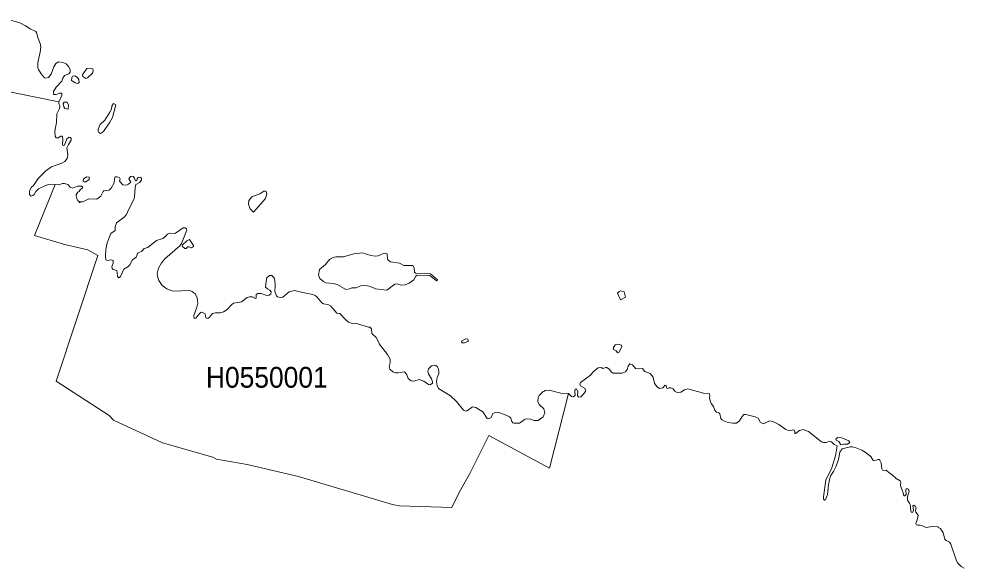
# Model space of a CAD drawing. Extents: x 369010 to 739155, y 6377141 to 6616555.
# Drawn here: x 445236 to 449782, y 6490349 to 6492992 of the extents above; entities that cross this region are included whole.
import ezdxf
from ezdxf.enums import TextEntityAlignment as Align

# ---------------------------------------------------------------- set-up
doc = ezdxf.new("R2010")
doc.units = 0
doc.header["$LTSCALE"] = 40
doc.layers.add('1', color=7, linetype='Continuous', lineweight=13)
doc.layers.add('2', color=7, linetype='Continuous')

msp = doc.modelspace()

# ---------------------------------------------------------------- linework, layer by layer
at = {"layer": '1'}
for points in [[(445001.04, 6492679.83), (445428.7, 6492593.93), (445443.43, 6492623.72), (445443.43, 6492631), (445440.12, 6492634.81), (445431.18, 6492635.14), (445415.13, 6492629.18), (445406.19, 6492628.19), (445403.38, 6492631), (445402.38, 6492642.59), (445416.12, 6492664.27), (445443.76, 6492693.4), (445447.57, 6492707.13), (445456.17, 6492719.38), (445477.19, 6492727.32), (445483.65, 6492735.27), (445483.65, 6492748.18), (445474.71, 6492763.24), (445464.45, 6492775.32), (445448.56, 6492782.93), (445427.71, 6492785.91), (445413.64, 6492778.13), (445405.03, 6492762.25), (445391.13, 6492725.67), (445379.05, 6492709.78), (445365.31, 6492706.8), (445359.85, 6492709.45), (445342.97, 6492728.32), (445330.39, 6492748.84), (445327.91, 6492757.12), (445327.91, 6492782.11), (445339, 6492831.92), (445341.64, 6492856.91), (445338.66, 6492873.46), (445328.9, 6492898.46), (445321.45, 6492927.58), (445317.31, 6492932.05), (445290.17, 6492944.96), (445268.66, 6492959.69), (445241.18, 6492973.93), (445174.65, 6492992.3)], [(447914.57, 6491182.34), (447906.29, 6491174.07), (447896.03, 6491174.73), (447882.29, 6491190.29), (447881.96, 6491190.29), (447791.43, 6490829.82), (447498.66, 6490987.88), (447407.63, 6490804.33), (447355.5, 6490713.64), (447321.07, 6490640.65), (447068.68, 6490648.76), (447034.75, 6490655.71), (446916.74, 6490690.96), (446582.59, 6490790.6), (446335.49, 6490848.19), (446188.36, 6490873.85), (446170.32, 6490882.45), (445928.02, 6490951.47), (445691.52, 6491062.02), (445671, 6491084.37), (445416.12, 6491248.55), (445616.05, 6491854.46), (445567.72, 6491880.77), (445449.22, 6491907.75), (445451.87, 6491907.75), (445311.19, 6491949.62), (445410.82, 6492195.39), (445399.9, 6492196.88), (445378.72, 6492195.23), (445364.65, 6492191.09), (445330.39, 6492173.88), (445317.98, 6492160.97), (445310.53, 6492147.9), (445304.24, 6492141.77), (445294.81, 6492138.63), (445287.19, 6492146.74), (445287.19, 6492165.27), (445296.46, 6492182.49), (445306.06, 6492189.77), (445329.4, 6492224.03), (445365.64, 6492261.76), (445393.45, 6492279.97), (445442.77, 6492297.35), (445458.32, 6492305.95), (445469.25, 6492320.68), (445471.56, 6492338.56), (445467.92, 6492371.82), (445474.71, 6492388.54), (445488.11, 6492409.06), (445488.45, 6492416.67), (445484.31, 6492421.8), (445479.18, 6492422.8), (445467.59, 6492414.69), (445455.51, 6492384.4), (445450.71, 6492382.75), (445447.57, 6492384.73), (445446.24, 6492390.03), (445447.9, 6492410.88), (445446.57, 6492423.96), (445443.43, 6492427.27), (445437.97, 6492427.27), (445425.39, 6492419.82), (445416.12, 6492420.15), (445411.32, 6492427.27), (445409.17, 6492452.42), (445417.44, 6492494.13), (445419.76, 6492535.67), (445431.84, 6492560.66), (445433.17, 6492571.92), (445429.03, 6492585.65), (445428.7, 6492593.93), (445001.04, 6492679.83)], [(445806.54, 6491860.91), (445802.08, 6491847.17), (445783.7, 6491832.78), (445770.96, 6491808.12), (445760.7, 6491799.18), (445741.17, 6491788.25), (445725.28, 6491751.84), (445720.48, 6491747.04), (445717.5, 6491746.71), (445711.54, 6491752.51), (445710.22, 6491772.37), (445707.24, 6491780.97), (445690.03, 6491786.1), (445686.22, 6491790.9), (445683.91, 6491800.83), (445690.36, 6491817.05), (445689.7, 6491828.97), (445681.42, 6491832.11), (445661.56, 6491830.13), (445655.77, 6491833.44), (445652.96, 6491850.98), (445655.77, 6491882.92), (445661.56, 6491915.03), (445678.44, 6491959.22), (445699.96, 6491974.45), (445699.96, 6491992.49), (445706.74, 6492010.36), (445742.82, 6492038.17), (445754.08, 6492050.25), (445763.68, 6492073.09), (445789.83, 6492123.9), (445793.3, 6492136.64), (445795.62, 6492179.84), (445800.09, 6492194.57), (445816.47, 6492204.83), (445826.57, 6492216.08), (445826.57, 6492224.69), (445821.27, 6492231.14), (445811.34, 6492229.82), (445806.21, 6492223.03), (445804.23, 6492215.09), (445800.42, 6492213.43), (445795.95, 6492216.08), (445792.48, 6492225.35), (445786.35, 6492233.63), (445782.55, 6492235.28), (445774.11, 6492233.63), (445765.83, 6492222.54), (445775.43, 6492206.15), (445764.84, 6492196.55), (445754.41, 6492191.42), (445737.03, 6492193.74), (445721.14, 6492210.62), (445723.3, 6492222.7), (445720.48, 6492229.49), (445709.56, 6492232.96), (445700.62, 6492232.14), (445696.15, 6492222.21), (445694.5, 6492203.01), (445680.76, 6492177.35), (445671.82, 6492168.75), (445646.17, 6492164.61), (445642.36, 6492161.63), (445631.44, 6492138.63), (445611.25, 6492125.22), (445573.85, 6492125.88), (445566.56, 6492123.9), (445543.89, 6492111.15), (445531.64, 6492111.15), (445529.16, 6492107.35), (445526.18, 6492111.82), (445528.17, 6492112.48), (445520.39, 6492116.28), (445514.76, 6492127.37), (445511.45, 6492140.28), (445512.11, 6492146.57), (445519.89, 6492157.83), (445527.17, 6492161.63), (445531.97, 6492169.91), (445542.9, 6492178.68), (445543.89, 6492182.15), (445537.43, 6492186.95), (445518.24, 6492186.95), (445494.24, 6492178.35), (445483.65, 6492183.15), (445471.56, 6492195.56), (445456.17, 6492200.69), (445446.24, 6492200.36), (445428.04, 6492193.08), (445410.82, 6492195.39)], [(445410.82, 6492195.39), (445311.19, 6491949.62), (445451.87, 6491907.75), (445449.22, 6491907.75), (445567.72, 6491880.77), (445616.05, 6491854.46), (445416.12, 6491248.55), (445671, 6491084.37), (445691.52, 6491062.02), (445928.02, 6490951.47), (446170.32, 6490882.45), (446188.36, 6490873.85), (446335.49, 6490848.19), (446582.59, 6490790.6), (446916.74, 6490690.96), (447034.75, 6490655.71), (447068.68, 6490648.76), (447321.07, 6490640.65), (447355.5, 6490713.64), (447407.63, 6490804.33), (447498.66, 6490987.88), (447791.43, 6490829.82), (447881.96, 6491190.29), (447846.05, 6491190.62), (447788.62, 6491205.68), (447769.42, 6491203.69), (447766.77, 6491200.88), (447759.99, 6491199.23), (447741.78, 6491180.69), (447735.49, 6491169.6), (447733.84, 6491150.9), (447740.79, 6491136.17), (447763.3, 6491116.47), (447768.1, 6491096.94), (447759.49, 6491078.08), (447735.99, 6491060.37), (447729.7, 6491058.88), (447716.79, 6491060.04), (447699.91, 6491066.16), (447677.9, 6491067.82), (447671.11, 6491065.17), (447651.25, 6491049.28), (447645.79, 6491046.96), (447620.3, 6491046.3), (447614.84, 6491048.95), (447608.72, 6491055.57), (447604.25, 6491070.3), (447598.79, 6491077.08), (447573.8, 6491088.5), (447547.31, 6491097.61), (447533.25, 6491099.76), (447518.19, 6491093.3), (447509.91, 6491074.11), (447497.33, 6491068.48), (447490.71, 6491069.47), (447469.86, 6491102.08), (447435.6, 6491122.76), (447419.38, 6491125.08), (447394.39, 6491106.21), (447387.93, 6491105.22), (447376.18, 6491109.36), (447342.92, 6491150.57), (447313.79, 6491178.87), (447256.19, 6491214.29), (447250.07, 6491228.35), (447247.26, 6491247.55), (447250.07, 6491266.75), (447257.35, 6491285.95), (447258.34, 6491298.86), (447255.53, 6491311.6), (447252.06, 6491318.06), (447243.28, 6491324.02), (447235.67, 6491325.67), (447222.26, 6491322.86), (447208.86, 6491308.96), (447205.55, 6491296.21), (447208.2, 6491283.47), (447222.26, 6491259.8), (447227.73, 6491246.39), (447227.73, 6491238.62), (447216.8, 6491232), (447207.54, 6491232.82), (447185.69, 6491249.21), (447162.68, 6491257.15), (447137.2, 6491248.55), (447125.28, 6491249.87), (447111.21, 6491261.29), (447104.26, 6491279.66), (447095.82, 6491291.41), (447090.36, 6491293.73), (447062.22, 6491288.27), (447049.48, 6491289.59), (447037.07, 6491294.06), (447022.83, 6491306.14), (447018.36, 6491319.22), (447024.49, 6491338.42), (447023.83, 6491355.13), (447010.42, 6491376.81), (446970.7, 6491428.12), (446970.7, 6491431.92)], [(446970.7, 6491431.92), (446956.96, 6491459.4), (446935.28, 6491478.27), (446934.29, 6491500.28), (446925.35, 6491508.39), (446918.9, 6491508.39), (446861.3, 6491526.26), (446835.81, 6491528.74), (446823.57, 6491533.54), (446810.49, 6491543.47), (446781.2, 6491574.26), (446766.96, 6491576.91), (446737.83, 6491609.18), (446724.1, 6491618.12), (446703.24, 6491620.93), (446695.3, 6491625.4), (446670.97, 6491654.86), (446662.7, 6491661.64), (446651.77, 6491666.44), (446602.78, 6491675.38), (446562.57, 6491685.31), (446537.57, 6491679.19), (446506.79, 6491653.04), (446495.37, 6491651.71), (446481.97, 6491655.52), (446476.83, 6491660.32), (446468.73, 6491680.51), (446470.38, 6491709.64), (446469.06, 6491735.13), (446464.59, 6491745.72), (446453.66, 6491756.97), (446443.57, 6491757.31), (446430.66, 6491746.05), (446428.18, 6491741.25), (446424.37, 6491700.87), (446433.31, 6491692.59), (446444.73, 6491687.13), (446450.85, 6491679.19), (446448.86, 6491668.6), (446440.59, 6491662.31), (446430, 6491660.98), (446403.19, 6491671.57), (446385.97, 6491671.24), (446379.19, 6491666.78), (446379.19, 6491647.91), (446376.04, 6491646.91), (446360.32, 6491654.2), (446346.25, 6491655.52), (446334.67, 6491651.38), (446308.19, 6491631.52), (446270.12, 6491623.58), (446259.53, 6491616.46), (446239.34, 6491594.45), (446221.46, 6491583.2), (446205.74, 6491577.07), (446183.07, 6491578.06), (446168, 6491574.26), (446152.61, 6491555.39), (446145.99, 6491550.26), (446136.72, 6491554.4), (446132.59, 6491573.27), (446115.21, 6491581.04), (446106.93, 6491575.91), (446088.4, 6491552.58), (446080.62, 6491551.25), (446078.14, 6491564.33), (446093.53, 6491604.71), (446097.33, 6491623.91), (446095.35, 6491649.4), (446086.74, 6491668.26), (446070.52, 6491681.17), (446057.61, 6491685.64), (445980.82, 6491682), (445968.08, 6491684.98), (445948.88, 6491692.92), (445926.87, 6491709.64), (445910.48, 6491732.65), (445904.69, 6491748.04), (445902.54, 6491767.24), (445908.16, 6491792.72), (445922.89, 6491818.05), (445939.28, 6491837.24), (446011.6, 6491900.63), (446019.88, 6491912.05), (446045.2, 6491975.11), (446043.21, 6491981.89), (446037.09, 6491986.36), (446027.49, 6491986.36), (445991.08, 6491961.04), (445984.63, 6491958.89), (445962.95, 6491961.37), (445951.69, 6491955.91), (445944.41, 6491947.3), (445929.35, 6491936.05), (445898.56, 6491926.45), (445857.35, 6491892.85), (445838.82, 6491887.56), (445827.23, 6491872.5), (445810.68, 6491866.7), (445806.54, 6491860.91)], [(449150.06, 6490831.48), (449168.1, 6490889.24), (449175.38, 6490937.4), (449161.64, 6490944.35), (449149.06, 6490956.93), (449138.8, 6490959.58), (449122.09, 6490953.12), (449109.34, 6490954.11), (449100.07, 6490956.93), (449036.85, 6491006.91), (449011.86, 6491016.68), (448993.82, 6491010.88), (448975.78, 6490997.31), (448971.97, 6490997.64), (448971.31, 6491004.76), (448967.84, 6491013.03), (448965.02, 6491014.36), (448944.67, 6491010.22), (448928.78, 6491017.17), (448894.52, 6491041.17), (448866.05, 6491055.57), (448849.5, 6491057.55), (448821.03, 6491043.49), (448806.63, 6491050.77), (448795.71, 6491070.96), (448780.32, 6491077.75), (448735.63, 6491088.84), (448726.53, 6491088.34), (448717.92, 6491078.9), (448704.85, 6491057.89), (448690.78, 6491047.62), (448673.57, 6491046.96), (448650.4, 6491050.44), (448633.19, 6491055.9), (448622.26, 6491062.69), (448615.97, 6491069.97), (448610.84, 6491091.81), (448606.71, 6491096.61), (448594.79, 6491100.42), (448586.51, 6491109.69), (448580.72, 6491127.23), (448569.14, 6491141.3), (448563.51, 6491154.21), (448560.2, 6491169.93), (448562.85, 6491179.7), (448561.52, 6491186.81), (448559.04, 6491189.63), (448532.06, 6491190.62), (448457.26, 6491212.47), (448439.88, 6491207), (448422.67, 6491196.74), (448405.45, 6491194.1), (448393.87, 6491200.88), (448386.25, 6491212.14), (448375.5, 6491217.6), (448366.39, 6491216.94), (448360.44, 6491213.79), (448356.13, 6491214.78), (448352, 6491227.2), (448346.86, 6491229.35), (448336.27, 6491216.94), (448320.55, 6491213.29), (448308.47, 6491221.4), (448296.22, 6491237.95), (448290.59, 6491268.41), (448275.2, 6491285.95), (448249.22, 6491295.22), (448238.46, 6491309.29), (448214.13, 6491308.46), (448205.03, 6491310.28), (448190.63, 6491327.82), (448177.22, 6491331.79), (448169.28, 6491320.87), (448164.48, 6491305.81), (448156.2, 6491293.73), (448139.82, 6491287.94), (448097.62, 6491287.61), (448089.67, 6491292.41), (448078.09, 6491306.14), (448066.5, 6491315.08), (448061.37, 6491315.08), (448046.97, 6491309.29), (448039.03, 6491314.75), (448025.29, 6491312.6), (448002.29, 6491295.22), (447987.56, 6491278.34), (447939.56, 6491242.75), (447937.24, 6491234.15), (447939.56, 6491226.2), (447961.9, 6491212.96), (447963.89, 6491199.56), (447951.14, 6491183.01), (447940.88, 6491174.07), (447930.29, 6491172.08), (447926.15, 6491179.2), (447926.48, 6491198.4), (447920.36, 6491212.47), (447913.58, 6491211.14), (447912.75, 6491199.56), (447914.57, 6491182.34)], [(449786.91, 6490349.36), (449771.85, 6490356.65), (449756.79, 6490372.37), (449750.67, 6490384.28), (449723.36, 6490463.89), (449716.24, 6490474.48), (449700.36, 6490482.43), (449694.56, 6490487.89), (449685.13, 6490519.34), (449673.38, 6490539.2), (449662.46, 6490545.32), (449661.79, 6490547.31), (449632.83, 6490548.8), (449604.03, 6490544.66), (449592.45, 6490550.12), (449584.5, 6490552.11), (449580.86, 6490554.92), (449575.24, 6490556.24), (449564.64, 6490555.58), (449558.19, 6490557.9), (449554.55, 6490563.36), (449555.21, 6490569.15), (449562.33, 6490586.36), (449565.14, 6490604.07), (449554.38, 6490618.8), (449553.39, 6490628.07), (449555.54, 6490639.66), (449552.4, 6490646.11), (449544.12, 6490652.24), (449539.49, 6490649.92), (449542.47, 6490628.07), (449539.16, 6490617.81), (449536.67, 6490616.16), (449531.54, 6490618.8), (449528.56, 6490635.85), (449529.23, 6490648.59), (449523.76, 6490662.5), (449514.5, 6490675.9), (449513.5, 6490680.7), (449514.83, 6490692.29), (449522.61, 6490718.93), (449519.29, 6490728.53), (449516.48, 6490731.02), (449507.71, 6490730.52), (449506.22, 6490727.54), (449507.38, 6490703.54), (449501.09, 6490696.43), (449498.11, 6490697.75), (449495.63, 6490702.22), (449493.64, 6490713.14), (449489.84, 6490719.26), (449480.24, 6490746.74), (449481.73, 6490762.79), (449478.58, 6490768.58), (449460.38, 6490780.17), (449438.2, 6490799.04), (449425.29, 6490807.48), (449412.21, 6490819.89), (449404.44, 6490818.4), (449394.5, 6490819.89), (449390.04, 6490827.67), (449386.89, 6490856.47), (449380.77, 6490869.38), (449377.46, 6490871.86), (449371.17, 6490872.19), (449355.45, 6490865.9), (449348.99, 6490867.06), (449338.07, 6490886.09), (449310.76, 6490906.62), (449293.55, 6490917.21), (449261.44, 6490930.28), (449249.19, 6490933.59), (449237.61, 6490933.59), (449199.54, 6490922.67), (449188.62, 6490906.62), (449182.16, 6490871.86), (449169.25, 6490837.27), (449157.17, 6490813.6), (449144.92, 6490794.24), (449140.13, 6490781.49), (449133.67, 6490749.39), (449128.54, 6490704.37), (449118.61, 6490677.23), (449115.13, 6490675.9), (449112.49, 6490677.56), (449110.33, 6490683.35), (449110, 6490691.63), (449120.93, 6490772.39), (449150.06, 6490831.48)]]:
    msp.add_lwpolyline(points, dxfattribs=at)
for points in [[(445578.98, 6492755.13), (445562.76, 6492754.14), (445543.23, 6492722.86), (445544.72, 6492715.74), (445558.78, 6492706.14), (445566.23, 6492709.12), (445590.89, 6492731.79), (445594.7, 6492741.72), (445592.38, 6492751.65)], [(445505.49, 6492718.06), (445494.9, 6492716.07), (445490.76, 6492710.94), (445489.77, 6492696.54), (445507.97, 6492684.13), (445517.9, 6492681.31), (445527.17, 6492685.45), (445524.36, 6492700.51), (445517.9, 6492710.94)], [(445470.9, 6492587.8), (445466.43, 6492591.94), (445454.85, 6492591.94), (445449.06, 6492584.33), (445452.37, 6492568.94), (445458.32, 6492560.99), (445473.05, 6492558.01), (445476.03, 6492577.87)], [(445643.69, 6492450.6), (445674.64, 6492494.79), (445687.22, 6492518.46), (445702.44, 6492578.87), (445692.51, 6492584.66), (445684.24, 6492573.07), (445682.75, 6492558.01), (445674.97, 6492542.79), (445650.64, 6492504.39), (445628.3, 6492484.53), (445618.37, 6492461.53), (445618.03, 6492452.26), (445621.51, 6492445.14), (445629.62, 6492441.33)], [(445564.25, 6492232.63), (445547.36, 6492223.36), (445545.71, 6492210.95), (445550.18, 6492207.48), (445559.12, 6492207.48), (445574.18, 6492219.56), (445574.84, 6492230.15)], [(446423.38, 6492163.29), (446415.27, 6492162.63), (446397.06, 6492150.21), (446358, 6492136.14), (446343.44, 6492117.77), (446342.11, 6492100.56), (446349.07, 6492078.55), (446366.11, 6492062.83), (446424.04, 6492127.37), (446429.67, 6492149.88), (446427.18, 6492160.97)], [(446057.61, 6491930.09), (446044.21, 6491924.63), (446023.35, 6491904.44), (446023.02, 6491899.31), (446034.61, 6491887.23), (446041.39, 6491887.23), (446047.68, 6491894.84), (446056.62, 6491896.16), (446067.21, 6491891.36), (446076.81, 6491897.16), (446077.14, 6491901.29)], [(446888.28, 6491866.7), (446849.22, 6491861.24), (446798.57, 6491847.17), (446761.5, 6491847.17), (446748.76, 6491844.36), (446733.04, 6491835.59), (446711.69, 6491810.1), (446684.38, 6491786.43), (446678.92, 6491760.78), (446685.37, 6491743.57), (446702.58, 6491727.85), (446714.17, 6491722.38), (446748.76, 6491719.57), (446768.29, 6491714.11), (446810.16, 6491690.11), (446828.03, 6491692.59), (446838.46, 6491698.88), (446860.8, 6491697.56), (446880.5, 6491707.99), (446906.15, 6491709.31), (446928.83, 6491704.51), (446952.82, 6491693.92), (447007.94, 6491686.64), (447046.33, 6491716.26), (447057.09, 6491716.92), (447076.29, 6491710.47), (447095.49, 6491713.12), (447114.69, 6491720.4), (447137.69, 6491736.78), (447147.95, 6491754.99), (447153.75, 6491758.3), (447213.99, 6491757.64), (447246.59, 6491732.31), (447252.06, 6491734.3), (447252.06, 6491737.11), (447218.46, 6491765.25), (447145.47, 6491768.39), (447141, 6491773.19), (447139.35, 6491794.05), (447132.89, 6491806.13), (447089.2, 6491804.97), (447068.02, 6491817.38), (447025.15, 6491823.18), (447011.41, 6491834.43), (447008.6, 6491861.57), (446995.69, 6491865.05), (446966.23, 6491852.64), (446952.16, 6491849.99), (446931.14, 6491853.3)], [(448134.69, 6491683.99), (448126.41, 6491681.17), (448118.8, 6491672.4), (448132.21, 6491641.12), (448156.87, 6491653.53), (448150.08, 6491678.53)], [(447400.51, 6491440.86), (447397.86, 6491451.79), (447387.27, 6491452.12), (447368.74, 6491442.52), (447367.74, 6491438.21), (447371.05, 6491433.41), (447381.65, 6491433.08)], [(448119.96, 6491427.46), (448106.22, 6491424.48), (448097.62, 6491407.26), (448098.61, 6491400.81), (448112.35, 6491395.68), (448118.14, 6491386.08), (448124.1, 6491386.41), (448139.49, 6491413.88), (448136.67, 6491421.99)], [(449197.89, 6490976.79), (449177.69, 6490977.78), (449169.25, 6490970.17), (449170.58, 6490964.38), (449183.16, 6490958.91), (449192.76, 6490942.53), (449206.66, 6490946.5), (449225.53, 6490946.01), (449236.45, 6490953.45), (449231.81, 6490962.06)]]:
    msp.add_lwpolyline(points, close=True, dxfattribs=at)

# ---------------------------------------------------------------- texts
at = {"layer": '2', "width": 0.95}
msp.add_text('H0550001', height=100, dxfattribs=at).set_placement((446429.84, 6491217.5), align=Align.CENTER)

doc.saveas('drawing.dxf')
